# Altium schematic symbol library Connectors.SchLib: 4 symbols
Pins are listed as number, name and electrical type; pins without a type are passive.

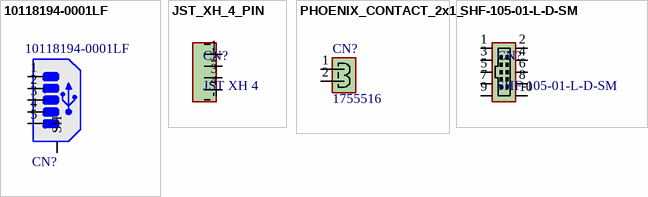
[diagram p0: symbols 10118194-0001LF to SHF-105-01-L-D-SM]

## 10118194-0001LF
designator CN?
Micro USB, Input Output Connectors, B TYPE RECEPTACLE with flange; Manufacturer: Amphenol
footprint 10118194-0001LF (Micro USB, Input Output Connectors, B TYPE RECEPTACLE with flange)
pins: 1 Pin 1, 2, 3, 4, 5, S1 SH, S2 SH, S3 SH, S4 SH, S5 SH, S6 SH

## JST_XH_4_PIN
designator CN?, comment JST XH 4
JST XH 4 Pin Connector; Manufacturer: JASO
footprint JST_XH_4-PIN (JST XH 4 pin connector)
pins: 1 Pin 1, 2 Pin 2, 3 Pin 3, 4 Pin 4

## PHOENIX_CONTACT_2x1_
designator CN?  Mfr Part Num.: 1755516  (hidden comment: *)
Pin header, straight, Straight, 5mm Pitch, 2 Poles, Phoenix Contact
footprint 1755516 (Pin header, straight, Straight, 5mm Pitch, 2 Poles, Phoenix Contact)
pins: 1 Pin 1, 2 Pin 2

## SHF-105-01-L-D-SM
designator CN?
Pin Header, Vertical, Wire-to-Board, 1.27 mm, 2 Rows, 10 Contacts, Surface Mount, SHF; Manufacturer: Samtec
footprint SHF-105-01-L-D-SM
pins: 1 Pin1 (power), 2 Pin2 (power), 3 (power), 4 (power), 5 (power), 6 (power), 7 (power), 8 (power), 9 (power), 10 (power)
